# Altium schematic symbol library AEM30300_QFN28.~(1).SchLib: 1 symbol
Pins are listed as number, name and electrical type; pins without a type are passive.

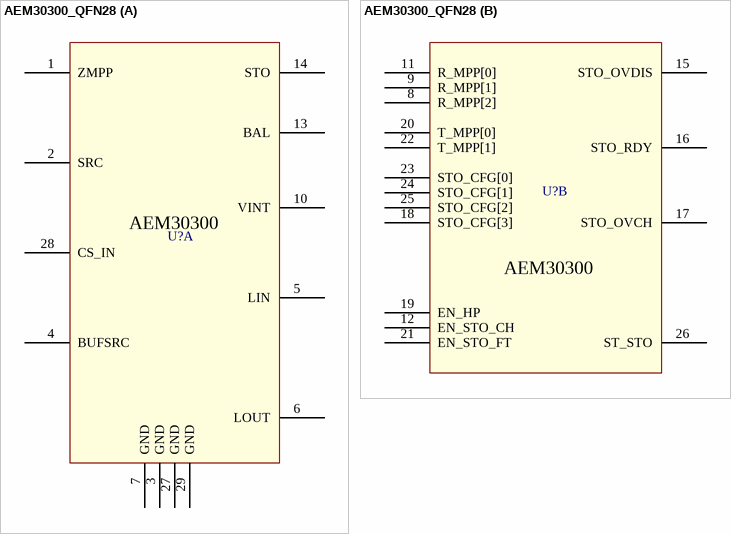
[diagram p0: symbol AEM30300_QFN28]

## AEM30300_QFN28
designator U?  (value not drawn)
part A pins: 1 ZMPP, 2 SRC, 3 GND, 4 BUFSRC, 5 LIN, 6 LOUT, 7 GND, 10 VINT, 13 BAL, 14 STO, 27 GND, 28 CS_IN, 29 GND
part B pins: 8 R_MPP[2], 9 R_MPP[1], 11 R_MPP[0], 12 EN_STO_CH, 15 STO_OVDIS, 16 STO_RDY, 17 STO_OVCH, 18 STO_CFG[3], 19 EN_HP, 20 T_MPP[0], 21 EN_STO_FT, 22 T_MPP[1], 23 STO_CFG[0], 24 STO_CFG[1], 25 STO_CFG[2], 26 ST_STO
